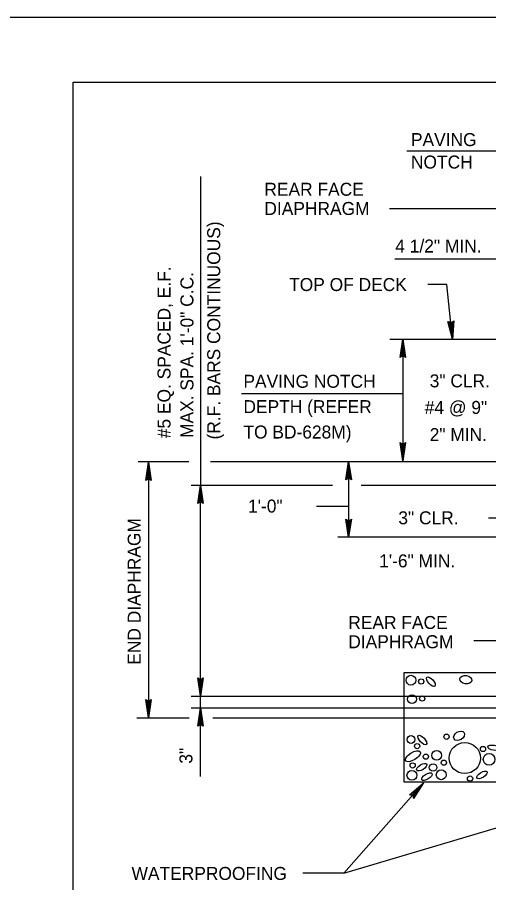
# Model space of a CAD drawing. Extents: x 638653 to 642302, y 298557 to 300414.
# Drawn here: x 639850.3 to 639959.2, y 300138.6 to 300338.5 of the extents above; entities that cross this region are included whole.
import ezdxf

# ---------------------------------------------------------------- set-up
doc = ezdxf.new("R2010")
doc.units = 0
doc.layers.add('1', color=7, linetype='Continuous')
doc.layers.add('PLT-BNDY', color=7, linetype='Continuous')

msp = doc.modelspace()

# ---------------------------------------------------------------- linework, layer by layer
at = {"layer": '1'}
for p, q in [((639863.16, 299759.52), (639863.16, 300323.52)), ((639863.16, 300323.52), (640649.16, 300323.52)), ((639940.26, 300307.7), (639968.7, 300307.7)), ((639892.6, 300301.72), (639892.6, 300230.43)), ((639968.54, 300294.31), (639936.25, 300294.31)), ((639937.45, 300282.69), (639983.15, 300282.69)), ((639945.13, 300276.9), (639949.48, 300276.9)), ((639950.8, 300264.18), (639949.52, 300276.83)), ((639936.33, 300264.18), (639984.27, 300264.18)), ((639939.32, 300264.18), (639939.32, 300236.05)), ((639939.32, 300251.53), (639902.04, 300251.53)), ((639878.17, 300235.9), (639889.92, 300235.9)), ((639880.57, 300235.74), (639880.57, 300176.68)), ((639894.9, 300235.9), (639941.66, 300235.9)), ((639926.81, 300235.9), (639926.81, 300218.4)), ((639940.41, 300235.9), (639965.89, 300235.9)), ((639890.41, 300230.43), (639923.06, 300230.43)), ((639892.6, 300163.15), (639892.6, 300230.43)), ((639929.73, 300230.43), (639969.95, 300230.43)), ((639926.81, 300225.52), (639919.4, 300225.52)), ((639959.08, 300222.91), (639968.54, 300222.91)), ((639986.82, 300218.4), (639924.28, 300218.4)), ((639968.7, 300194.49), (639955.71, 300194.49)), ((639890.41, 300181.68), (639970.26, 300181.68)), ((639890.41, 300179.02), (639971.73, 300179.02)), ((639877.91, 300176.68), (639889.96, 300176.68)), ((639895.43, 300176.68), (639964.27, 300176.68)), ((639925.7, 300140.84), (639944.14, 300161.66)), ((639925.7, 300140.84), (639966.91, 300153.09)), ((639925.7, 300140.84), (639916.24, 300140.84))]:
    msp.add_line(p, q, dxfattribs=at)
for points in [[(639950.96, 300268.24), (639950.65, 300268.09), (639950.8, 300264.18), (639950.96, 300268.24), (639951.11, 300268.4), (639950.8, 300264.18), (639950.18, 300268.09), (639949.86, 300268.09), (639950.8, 300264.18), (639949.71, 300268.24), (639949.86, 300268.09)], [(639950.96, 300268.24), (639950.65, 300268.09), (639950.8, 300264.18), (639950.96, 300268.24), (639951.11, 300268.4), (639950.8, 300264.18), (639950.18, 300268.09), (639949.86, 300268.09), (639950.8, 300264.18), (639949.71, 300268.24), (639949.86, 300268.09)], [(639938.85, 300260.12), (639939.16, 300260.27), (639939.32, 300264.18), (639938.85, 300260.12), (639938.7, 300259.96), (639939.32, 300264.18), (639939.48, 300260.27), (639939.79, 300260.12), (639939.32, 300264.18), (639939.95, 300259.96), (639939.79, 300260.12)], [(639938.85, 300260.12), (639939.16, 300260.27), (639939.32, 300264.18), (639938.85, 300260.12), (639938.7, 300259.96), (639939.32, 300264.18), (639939.48, 300260.27), (639939.79, 300260.12), (639939.32, 300264.18), (639939.95, 300259.96), (639939.79, 300260.12)], [(639939.79, 300240.12), (639939.48, 300239.96), (639939.32, 300236.05), (639939.79, 300240.12), (639939.95, 300240.27), (639939.32, 300236.05), (639939.16, 300239.96), (639938.85, 300240.12), (639939.32, 300236.05), (639938.7, 300240.27), (639938.85, 300240.12)], [(639880.1, 300231.68), (639880.41, 300231.84), (639880.57, 300235.74), (639880.1, 300231.68), (639879.95, 300231.52), (639880.57, 300235.74), (639880.73, 300231.84), (639881.04, 300231.68), (639880.57, 300235.74), (639881.2, 300231.52), (639881.04, 300231.68)], [(639880.1, 300231.68), (639880.41, 300231.84), (639880.57, 300235.74), (639880.1, 300231.68), (639879.95, 300231.52), (639880.57, 300235.74), (639880.73, 300231.84), (639881.04, 300231.68), (639880.57, 300235.74), (639881.2, 300231.52), (639881.04, 300231.68)], [(639926.34, 300231.84), (639926.66, 300231.99), (639926.81, 300235.9), (639926.34, 300231.84), (639926.19, 300231.68), (639926.81, 300235.9), (639926.97, 300231.99), (639927.28, 300231.84), (639926.81, 300235.9), (639927.44, 300231.68), (639927.28, 300231.84)], [(639926.34, 300231.84), (639926.66, 300231.99), (639926.81, 300235.9), (639926.34, 300231.84), (639926.19, 300231.68), (639926.81, 300235.9), (639926.97, 300231.99), (639927.28, 300231.84), (639926.81, 300235.9), (639927.44, 300231.68), (639927.28, 300231.84)], [(639892.13, 300226.37), (639892.45, 300226.52), (639892.6, 300230.43), (639892.13, 300226.37), (639891.98, 300226.21), (639892.6, 300230.43), (639892.76, 300226.52), (639893.07, 300226.37), (639892.6, 300230.43), (639893.23, 300226.21), (639893.07, 300226.37)], [(639927.28, 300222.46), (639926.97, 300222.3), (639926.81, 300218.4), (639927.28, 300222.46), (639927.44, 300222.62), (639926.81, 300218.4), (639926.66, 300222.3), (639926.34, 300222.46), (639926.81, 300218.4), (639926.19, 300222.62), (639926.34, 300222.46)], [(639893.07, 300185.74), (639892.76, 300185.59), (639892.6, 300181.68), (639893.07, 300185.74), (639893.23, 300185.9), (639892.6, 300181.68), (639892.45, 300185.59), (639892.13, 300185.74), (639892.6, 300181.68), (639891.98, 300185.9), (639892.13, 300185.74)], [(639881.04, 300180.74), (639880.73, 300180.59), (639880.57, 300176.68), (639881.04, 300180.74), (639881.2, 300180.9), (639880.57, 300176.68), (639880.41, 300180.59), (639880.1, 300180.74), (639880.57, 300176.68), (639879.95, 300180.9), (639880.1, 300180.74)], [(639892.13, 300174.96), (639892.45, 300175.12), (639892.6, 300179.02), (639892.13, 300174.96), (639891.98, 300174.8), (639892.6, 300179.02), (639892.76, 300175.12), (639893.07, 300174.96), (639892.6, 300179.02), (639893.23, 300174.8), (639893.07, 300174.96)], [(639941.11, 300158.92), (639941.45, 300158.83), (639944.14, 300161.66), (639941.11, 300158.92), (639940.89, 300158.91), (639944.14, 300161.66), (639941.68, 300158.63), (639941.81, 300158.3), (639944.14, 300161.66), (639941.83, 300158.08), (639941.81, 300158.3)]]:
    msp.add_lwpolyline(points, dxfattribs=at)
msp.add_lwpolyline([(639967.1, 300187.08), (639939.56, 300187.08), (639939.56, 300161.89), (639967.1, 300161.89)], close=True, dxfattribs=at)
for centre, radius in [((639941.19, 300185.39), 1.13), ((639943.57, 300185.09), 0.605), ((639941.45, 300181.01), 1.01), ((639943.81, 300181.15), 0.605), ((639941.23, 300171.69), 0.9), ((639949.42, 300172.33), 0.605), ((639942.62, 300170.16), 0.605), ((639953.63, 300167.41), 3.6), ((639957.85, 300169.49), 0.605), ((639944.65, 300167.73), 0.605), ((639947.14, 300168.03), 1.13), ((639959.26, 300167.1), 1.35), ((639941.59, 300165.69), 0.605), ((639946.3, 300165.22), 0.871), ((639948.81, 300166.33), 0.605), ((639941.42, 300163.42), 1.13), ((639948.19, 300163.54), 1.13), ((639954.86, 300162.67), 0.605)]:
    msp.add_circle(centre, radius, dxfattribs=at)
for centre, major_axis, ratio in [((639945.82, 300185.04), (0.91, -1.02), 0.438009), ((639953.88, 300185.52), (1.36, -0.2), 0.696126), ((639952.33, 300172.54), (1.17, 0.72), 0.696126), ((639943.83, 300171.57), (0.91, -1.02), 0.438009), ((639960.33, 300169.79), (1.36, -0.2), 0.438009), ((639941.65, 300167.82), (1.68, 1.04), 0.438009), ((639943.7, 300165.29), (1.17, 0.72), 0.438009), ((639944.88, 300163.09), (1.17, 0.72), 0.438009), ((639957.62, 300163.51), (1.17, 0.72), 0.438009)]:
    msp.add_ellipse(centre, major_axis=major_axis, ratio=ratio, dxfattribs=at)
at = {"layer": 'PLT-BNDY'}
msp.add_lwpolyline([(639823.16, 300338.52), (640664.16, 300338.52), (640664.16, 299744.52), (639823.16, 299744.52)], close=True, dxfattribs=at)

# ---------------------------------------------------------------- texts
at = {"layer": '1'}
for s, p in [('PAVING', (639941.2, 300308.77)), ('NOTCH', (639941.2, 300303.59)), ('REAR FACE', (639907.35, 300297.3)), ('DIAPHRAGM', (639907.35, 300292.86)), ('4 1/2" MIN.', (639937.59, 300284.19)), ('TOP OF DECK', (639913.06, 300275.29)), ('PAVING NOTCH', (639902.51, 300252.94)), ('3" CLR.', (639945.54, 300253.04)), ('DEPTH (REFER', (639902.51, 300247.08)), ('#4 @ 9"', (639944.39, 300246.9)), ('TO BD-628M)', (639902.51, 300241.22)), ('2" MIN.', (639945.53, 300240.62)), ('1\'-0"', (639903.57, 300224.11)), ('3" CLR.', (639938.29, 300221.4)), ('1\'-6" MIN.', (639933.86, 300211.46)), ('REAR FACE', (639926.73, 300197.22)), ('DIAPHRAGM', (639926.73, 300192.78)), ('WATERPROOFING', (639876.67, 300139.25))]:
    msp.add_text(s, height=3, dxfattribs=at).set_placement(p)
for s, p in [('(R.F. BARS CONTINUOUS)', (639897.15, 300241)), ('#5 EQ. SPACED, E.F.', (639885.67, 300241.29)), ('MAX. SPA. 1\'-0" C.C.', (639890.96, 300241.36)), ('END DIAPHRAGM', (639878.77, 300188.96)), ('3"', (639890.72, 300166.11))]:
    msp.add_text(s, height=3, rotation=90, dxfattribs=at).set_placement(p)

doc.saveas('drawing.dxf')
